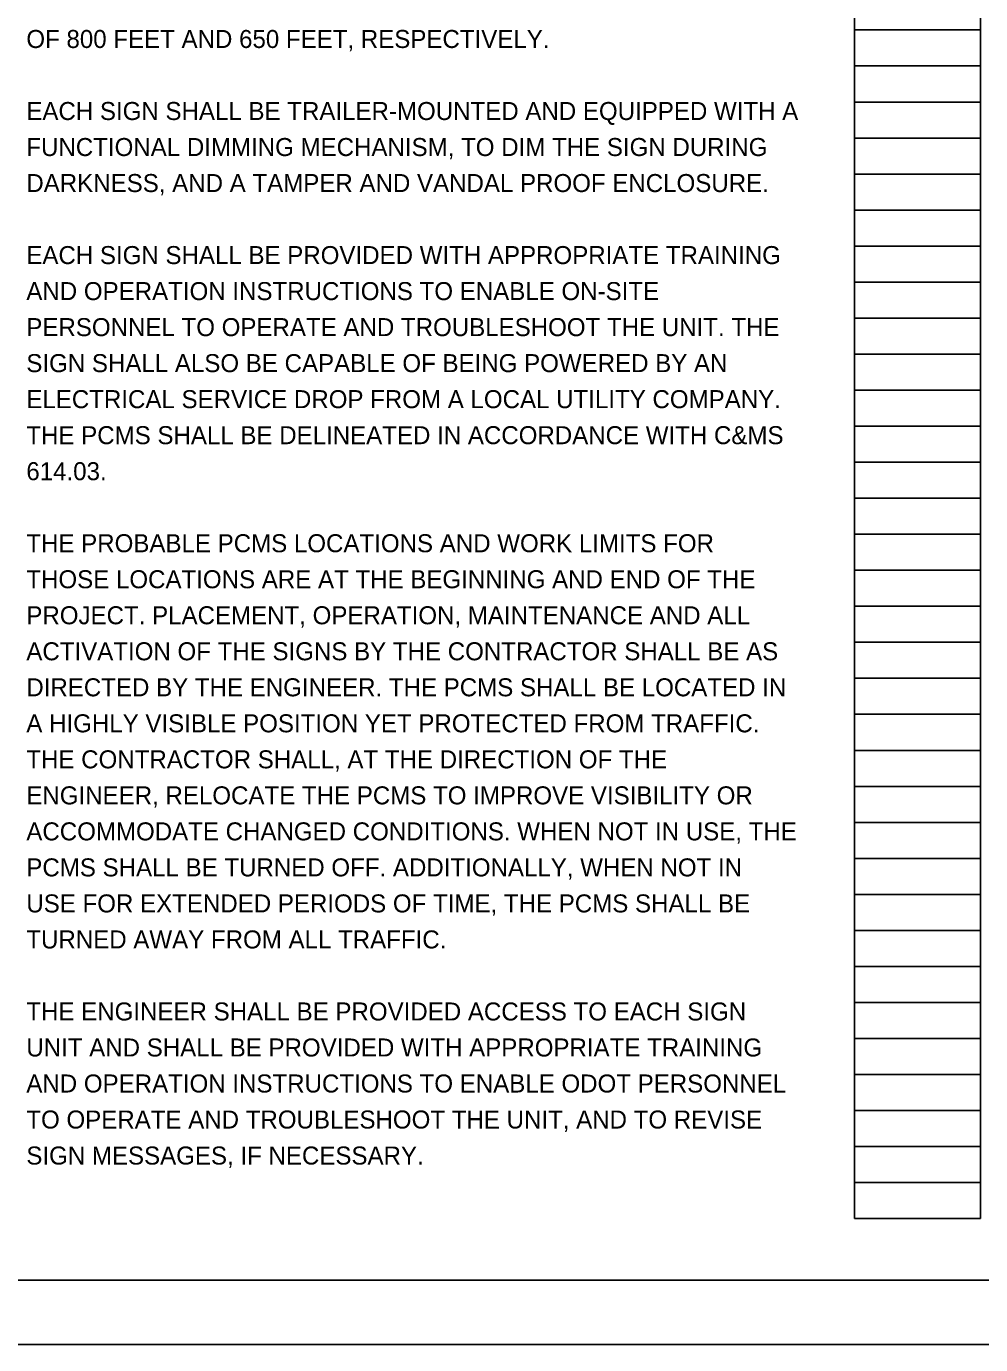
# Model space of a CAD drawing. Extents: x -50 to 112, y -27 to 22.
# Drawn here: x 56.24 to 63.66, y 0 to 10.25 of the extents above; entities that cross this region are included whole.
import ezdxf

# ---------------------------------------------------------------- set-up
doc = ezdxf.new("R2010")
doc.units = 0
for name, color, linetype in [('SC_Scratch1', 7, 'Continuous'), ('SH_Border', 7, 'Continuous'), ('SH_Cut_Line', 7, 'Continuous'), ('SH_Text', 7, 'Continuous')]:
    doc.layers.add(name, color=color, linetype=linetype)

msp = doc.modelspace()

# ---------------------------------------------------------------- linework, layer by layer
at = {"layer": 'SC_Scratch1'}
for p, q in [((62.68, 0.98), (62.68, 21.14)), ((63.66, 0.98), (63.66, 21.14)), ((62.68, 10.22), (63.66, 10.22)), ((62.68, 9.94), (63.66, 9.94)), ((62.68, 9.66), (63.66, 9.66)), ((62.68, 9.38), (63.66, 9.38)), ((62.68, 9.1), (63.66, 9.1)), ((62.68, 8.82), (63.66, 8.82)), ((62.68, 8.54), (63.66, 8.54)), ((62.68, 8.26), (63.66, 8.26)), ((62.68, 7.98), (63.66, 7.98)), ((62.68, 7.7), (63.66, 7.7)), ((62.68, 7.42), (63.66, 7.42)), ((62.68, 7.14), (63.66, 7.14)), ((62.68, 6.86), (63.66, 6.86)), ((62.68, 6.58), (63.66, 6.58)), ((62.68, 6.3), (63.66, 6.3)), ((62.68, 6.02), (63.66, 6.02)), ((62.68, 5.74), (63.66, 5.74)), ((62.68, 5.46), (63.66, 5.46)), ((62.68, 5.18), (63.66, 5.18)), ((62.68, 4.9), (63.66, 4.9)), ((62.68, 4.62), (63.66, 4.62)), ((62.68, 4.34), (63.66, 4.34)), ((62.68, 4.06), (63.66, 4.06)), ((62.68, 3.78), (63.66, 3.78)), ((62.68, 3.5), (63.66, 3.5)), ((62.68, 3.22), (63.66, 3.22)), ((62.68, 2.94), (63.66, 2.94)), ((62.68, 2.66), (63.66, 2.66)), ((62.68, 2.38), (63.66, 2.38)), ((62.68, 2.1), (63.66, 2.1)), ((62.68, 1.82), (63.66, 1.82)), ((62.68, 1.54), (63.66, 1.54)), ((62.68, 1.26), (63.66, 1.26)), ((62.68, 0.98), (63.66, 0.98))]:
    msp.add_line(p, q, dxfattribs=at)
at = {"layer": 'SH_Border'}
msp.add_lwpolyline([(40.5, 21.5), (72.5, 21.5), (72.5, 0.5), (40.5, 0.5)], close=True, dxfattribs=at)
at = {"layer": 'SH_Cut_Line'}
msp.add_lwpolyline([(39, 0), (73, 0), (73, 22), (39, 22)], close=True, dxfattribs=at)

# ---------------------------------------------------------------- texts
at = {"layer": 'SH_Text'}
for s, p in [('OF 800 FEET AND 650 FEET, RESPECTIVELY.', (56.24, 10.08)), ('EACH SIGN SHALL BE TRAILER-MOUNTED AND EQUIPPED WITH A ', (56.24, 9.52)), ('FUNCTIONAL DIMMING MECHANISM, TO DIM THE SIGN DURING ', (56.24, 9.24)), ('DARKNESS, AND A TAMPER AND VANDAL PROOF ENCLOSURE.', (56.24, 8.96)), ('EACH SIGN SHALL BE PROVIDED WITH APPROPRIATE TRAINING ', (56.24, 8.4)), ('AND OPERATION INSTRUCTIONS TO ENABLE ON-SITE ', (56.24, 8.12)), ('PERSONNEL TO OPERATE AND TROUBLESHOOT THE UNIT. THE ', (56.24, 7.84)), ('SIGN SHALL ALSO BE CAPABLE OF BEING POWERED BY AN ', (56.24, 7.56)), ('ELECTRICAL SERVICE DROP FROM A LOCAL UTILITY COMPANY. ', (56.24, 7.28)), ('THE PCMS SHALL BE DELINEATED IN ACCORDANCE WITH C&MS ', (56.24, 7)), ('614.03.', (56.24, 6.72)), ('THE PROBABLE PCMS LOCATIONS AND WORK LIMITS FOR ', (56.24, 6.16)), ('THOSE LOCATIONS ARE AT THE BEGINNING AND END OF THE ', (56.24, 5.88)), ('PROJECT. PLACEMENT, OPERATION, MAINTENANCE AND ALL ', (56.24, 5.6)), ('ACTIVATION OF THE SIGNS BY THE CONTRACTOR SHALL BE AS ', (56.24, 5.32)), ('DIRECTED BY THE ENGINEER. THE PCMS SHALL BE LOCATED IN ', (56.24, 5.04)), ('A HIGHLY VISIBLE POSITION YET PROTECTED FROM TRAFFIC. ', (56.24, 4.76)), ('THE CONTRACTOR SHALL, AT THE DIRECTION OF THE ', (56.24, 4.48)), ('ENGINEER, RELOCATE THE PCMS TO IMPROVE VISIBILITY OR ', (56.24, 4.2)), ('ACCOMMODATE CHANGED CONDITIONS. WHEN NOT IN USE, THE ', (56.24, 3.92)), ('PCMS SHALL BE TURNED OFF. ADDITIONALLY, WHEN NOT IN ', (56.24, 3.64)), ('USE FOR EXTENDED PERIODS OF TIME, THE PCMS SHALL BE ', (56.24, 3.36)), ('TURNED AWAY FROM ALL TRAFFIC.', (56.24, 3.08)), ('THE ENGINEER SHALL BE PROVIDED ACCESS TO EACH SIGN ', (56.24, 2.52)), ('UNIT AND SHALL BE PROVIDED WITH APPROPRIATE TRAINING ', (56.24, 2.24)), ('AND OPERATION INSTRUCTIONS TO ENABLE ODOT PERSONNEL ', (56.24, 1.96)), ('TO OPERATE AND TROUBLESHOOT THE UNIT, AND TO REVISE ', (56.24, 1.68)), ('SIGN MESSAGES, IF NECESSARY.', (56.24, 1.4))]:
    msp.add_text(s, height=0.14, dxfattribs=at).set_placement(p)

doc.saveas('drawing.dxf')
